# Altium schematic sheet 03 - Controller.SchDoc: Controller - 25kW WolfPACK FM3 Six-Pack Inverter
size 431 x 279 mm; Date: 01/2024; DocumentNumber: CRD25DA12N-FMC; Revision: 1.2; SheetNumber: 3; SheetTotal: 8; SheetSize: B
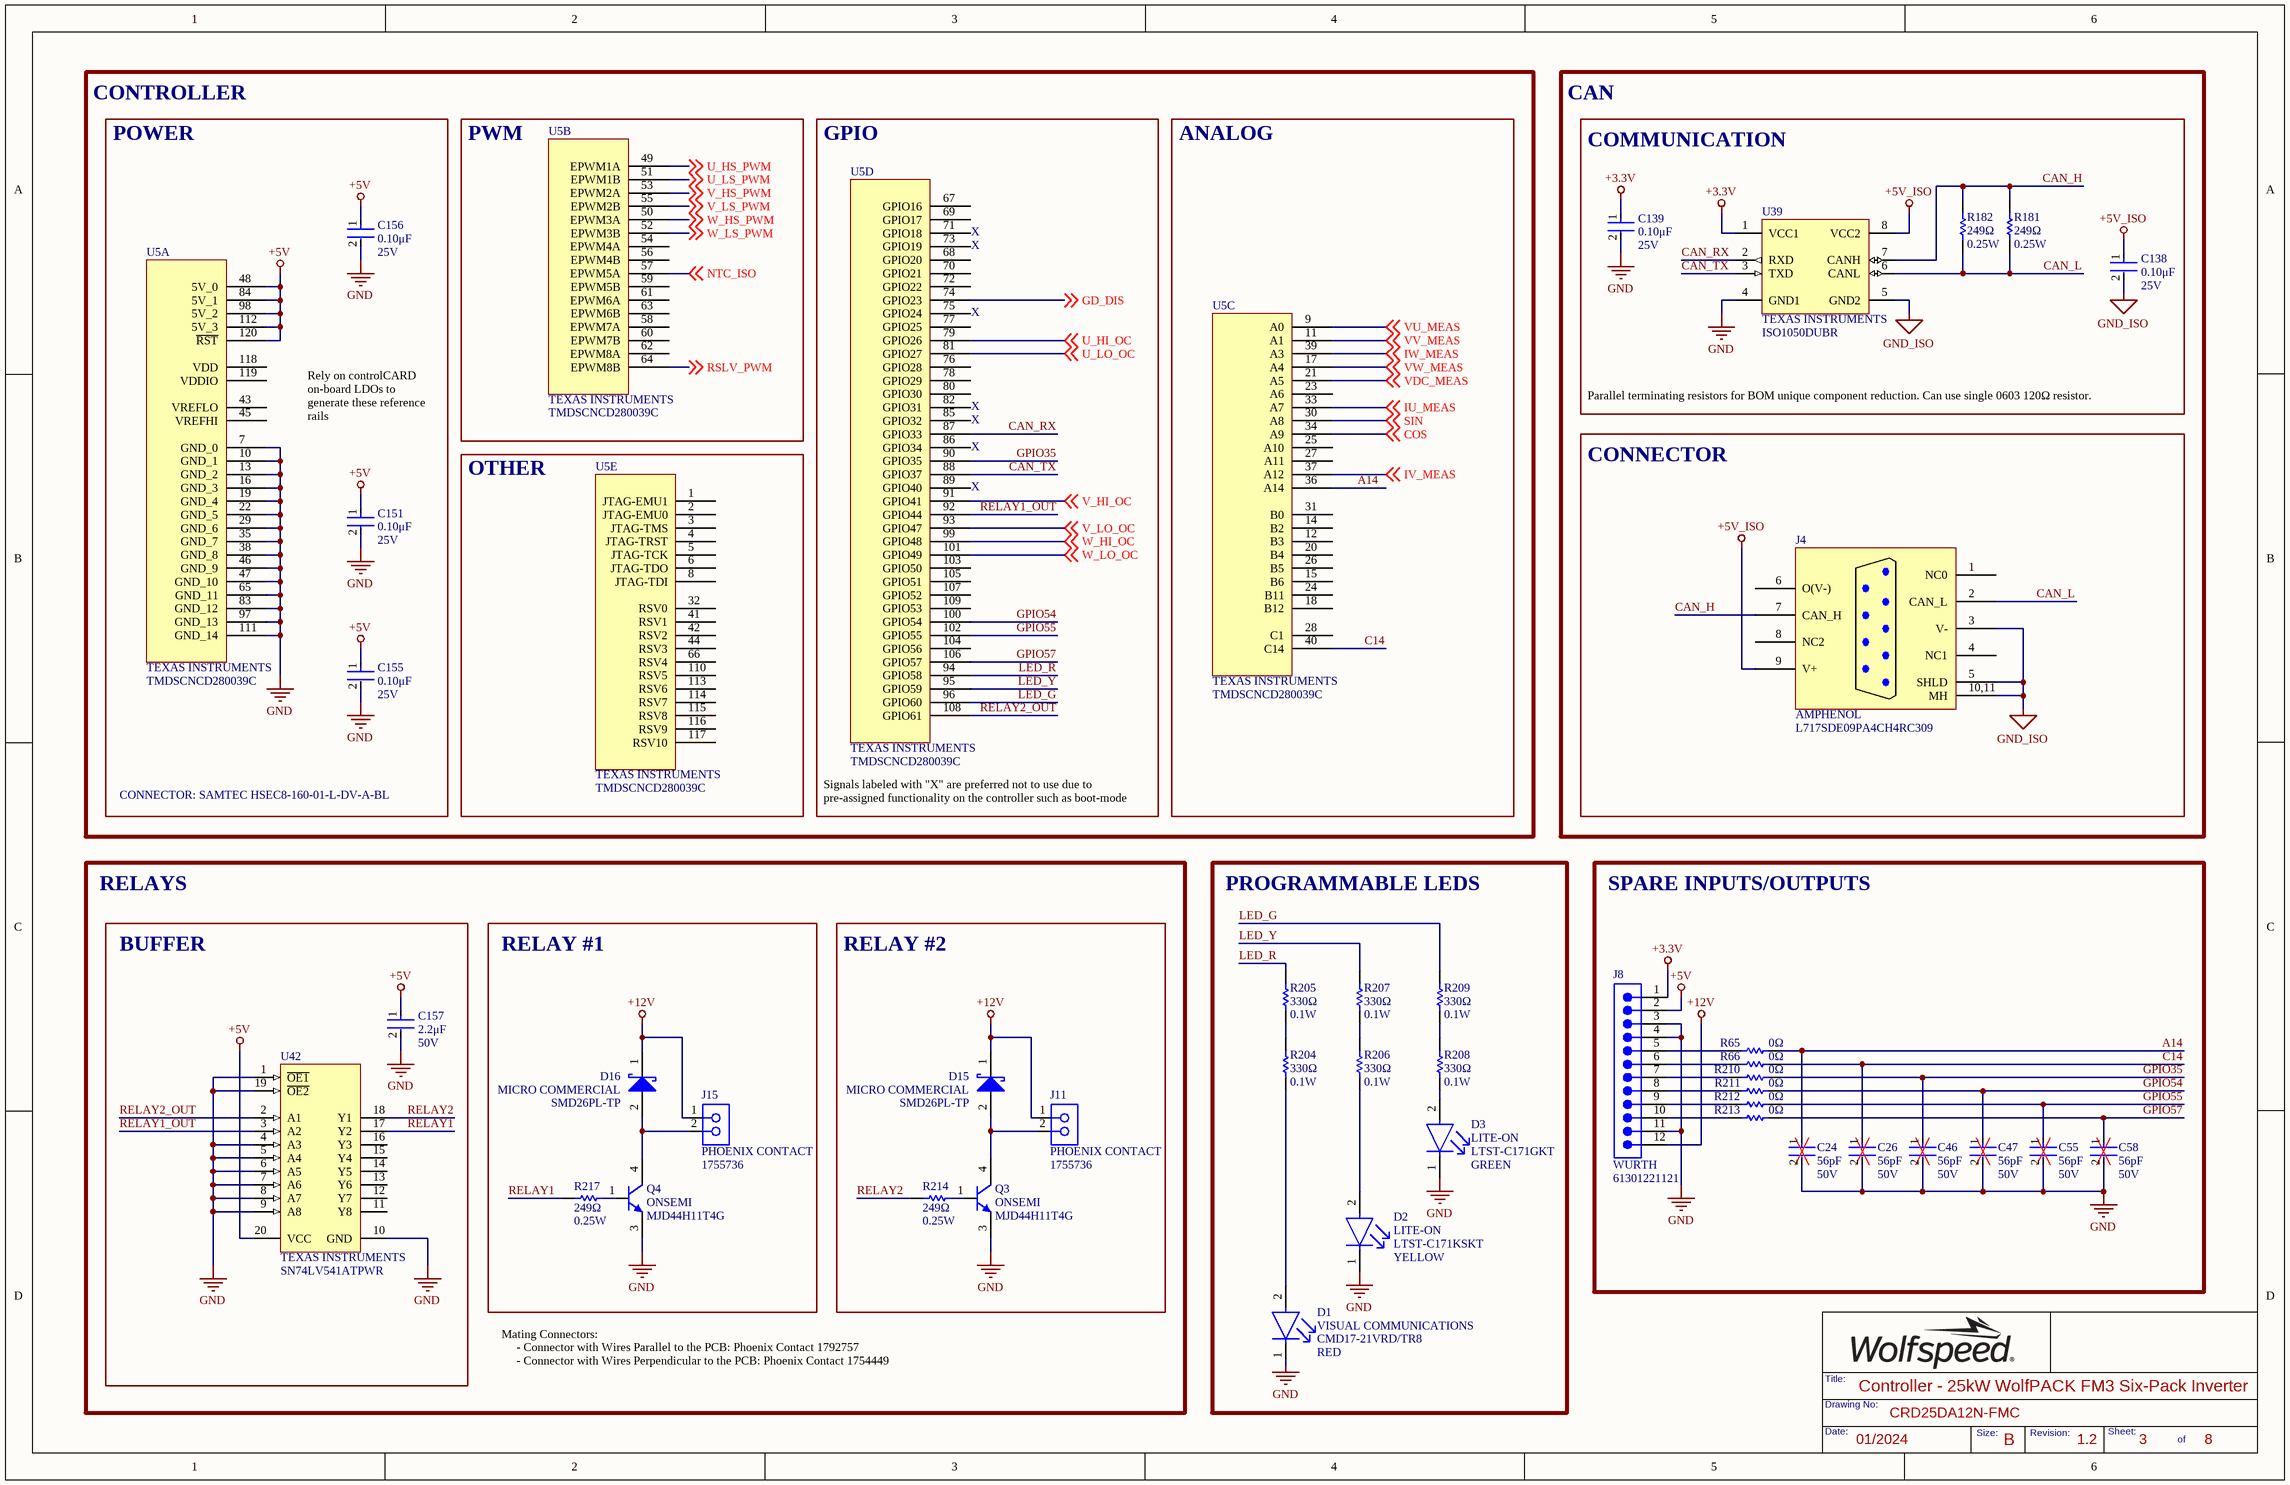
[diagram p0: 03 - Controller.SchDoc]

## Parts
C24  Capacitance: 56pF  Voltage Rating: 50V  [FP-C0603C-CF-IPC_B]  (hidden comment: CL10C560JB8NNNC)
C26  Capacitance: 56pF  Voltage Rating: 50V  [FP-C0603C-CF-IPC_B]  (hidden comment: CL10C560JB8NNNC)
C46  Capacitance: 56pF  Voltage Rating: 50V  [FP-C0603C-CF-IPC_B]  (hidden comment: CL10C560JB8NNNC)
C47  Capacitance: 56pF  Voltage Rating: 50V  [FP-C0603C-CF-IPC_B]  (hidden comment: CL10C560JB8NNNC)
C55  Capacitance: 56pF  Voltage Rating: 50V  [FP-C0603C-CF-IPC_B]  (hidden comment: CL10C560JB8NNNC)
C58  Capacitance: 56pF  Voltage Rating: 50V  [FP-C0603C-CF-IPC_B]  (hidden comment: CL10C560JB8NNNC)
C138  Voltage Rating: 25V  Capacitance: 0.10μF  [FP-C0603C-CF-IPC_B]  (hidden comment: C0603C104K3RACTU)
C139  Voltage Rating: 25V  Capacitance: 0.10μF  [FP-C0603C-CF-IPC_B]  (hidden comment: C0603C104K3RACTU)
C151  Voltage Rating: 25V  Capacitance: 0.10μF  [FP-C0603C-CF-IPC_B]  (hidden comment: C0603C104K3RACTU)
C155  Voltage Rating: 25V  Capacitance: 0.10μF  [FP-C0603C-CF-IPC_B]  (hidden comment: C0603C104K3RACTU)
C156  Voltage Rating: 25V  Capacitance: 0.10μF  [FP-C0603C-CF-IPC_B]  (hidden comment: C0603C104K3RACTU)
C157  Voltage Rating: 50V  Capacitance: 2.2μF  [FP-C0603C-CF-IPC_B]  (hidden comment: GRT188R61H225ME13D)
D1  value RED  Manufacturer: VISUAL COMMUNICATIONS  [FP-LTST-C171GKT-MFG-RED]  (hidden comment: CMD17-21VRD/TR8)
D2  LTST-C171KSKT  value YELLOW  Manufacturer: LITE-ON  [FP-LTST-C171GKT-MFG-YELLOW]
D3  value GREEN  Manufacturer: LITE-ON  [FP-LTST-C171GKT-MFG]  (hidden comment: LTST-C171GKT)
D15  SMD26PL-TP  Manufacturer: MICRO COMMERCIAL  [ONSC-SOD-123FL-2-498-01_V]
D16  SMD26PL-TP  Manufacturer: MICRO COMMERCIAL  [ONSC-SOD-123FL-2-498-01_V]
J4  Manufacturer: AMPHENOL  [L717SDE09PA4CH4RC309]  (hidden comment: L717SDE09PA4CH4RC309)
J8  Manufacturer Print: WURTH  [FP-61301221121-MFG]  (hidden comment: 61301221121)
J11  Manufacturer: PHOENIX CONTACT  [1755736]  (hidden comment: 1755736)
J15  Manufacturer: PHOENIX CONTACT  [1755736]  (hidden comment: 1755736)
Q3  Manufacturer: ONSEMI  [ONSC-DPAK-3-369C-01_V]  (hidden comment: MJD44H11T4G)
Q4  Manufacturer: ONSEMI  [ONSC-DPAK-3-369C-01_V]  (hidden comment: MJD44H11T4G)
R65  Resistance: 0Ω  [FP-MCR03-IPC_B]  (hidden comment: CRCW06030000Z0EB)
R66  Resistance: 0Ω  [FP-MCR03-IPC_B]  (hidden comment: CRCW06030000Z0EB)
R181  Resistance: 249Ω  Power Rating: 0.25W  [FP-MCR18-IPC_A]  (hidden comment: RC1206FR-07249RL)
R182  Resistance: 249Ω  Power Rating: 0.25W  [FP-MCR18-IPC_A]  (hidden comment: RC1206FR-07249RL)
R204  Resistance: 330Ω  Power Rating: 0.1W  [FP-MCR03-IPC_B]  (hidden comment: RC0603FR-13330RL)
R205  Resistance: 330Ω  Power Rating: 0.1W  [FP-MCR03-IPC_B]  (hidden comment: RC0603FR-13330RL)
R206  Resistance: 330Ω  Power Rating: 0.1W  [FP-MCR03-IPC_B]  (hidden comment: RC0603FR-13330RL)
R207  Resistance: 330Ω  Power Rating: 0.1W  [FP-MCR03-IPC_B]  (hidden comment: RC0603FR-13330RL)
R208  Resistance: 330Ω  Power Rating: 0.1W  [FP-MCR03-IPC_B]  (hidden comment: RC0603FR-13330RL)
R209  Resistance: 330Ω  Power Rating: 0.1W  [FP-MCR03-IPC_B]  (hidden comment: RC0603FR-13330RL)
R210  Resistance: 0Ω  [FP-MCR03-IPC_B]  (hidden comment: CRCW06030000Z0EB)
R211  Resistance: 0Ω  [FP-MCR03-IPC_B]  (hidden comment: CRCW06030000Z0EB)
R212  Resistance: 0Ω  [FP-MCR03-IPC_B]  (hidden comment: CRCW06030000Z0EB)
R213  Resistance: 0Ω  [FP-MCR03-IPC_B]  (hidden comment: CRCW06030000Z0EB)
R214  Resistance: 249Ω  Power Rating: 0.25W  [FP-MCR18-IPC_A]  (hidden comment: RC1206FR-07249RL)
R217  Resistance: 249Ω  Power Rating: 0.25W  [FP-MCR18-IPC_A]  (hidden comment: RC1206FR-07249RL)
U5  TMDSCNCD280039C  Manufacturer: TEXAS INSTRUMENTS  [TMDSCNCD280039C]  (parts A,B,C,D,E of 5)
U39  ISO1050DUBR  Manufacturer Print: TEXAS INSTRUMENTS  [DUB0008A_M]
U42  Manufacturer: TEXAS INSTRUMENTS  [PW0020A_L]  (hidden comment: SN74LV541ATPWR)

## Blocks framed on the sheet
POWER: C151 C155 C156 U5
PWM: U5
GPIO: U5
ANALOG: U5
COMMUNICATION: C138 C139 R181 R182 U39
CONNECTOR: J4
OTHER: U5
PROGRAMMABLE LEDS: D1-D3 R204-R209
SPARE INPUTS/OUTPUTS: C24 C26 C46 C47 C55 C58 J8 R65 R66 R210-R213
BUFFER: C157 U42
RELAY #1: D16 J15 Q4 R217
RELAY #2: D15 J11 Q3 R214

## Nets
+3.3V: C139.1 J8.1 U39.1(VCC1)
+5V: C151.1 C155.1 C156.1 C157.1 J8.2 U5.48(5V_0) U5.84(5V_1) U5.98(5V_2) U5.112(5V_3) U5.120(~{RST}) U42.20(VCC)
+5V_ISO: C138.1 J4.9(V+) U39.8(VCC2)
+12V: D15.1(K) D16.1(K) J8.12 J11.1 J15.1
GND: C24.2 C26.2 C46.2 C47.2 C55.2 C58.2 C139.2 C151.2 C155.2 C156.2 C157.2 D1.1(C) D2.1(C) D3.1(C) J8.3 J8.4 J8.11 Q3.3(E) Q4.3(E) U5.7(GND_0) U5.10(GND_1) U5.13(GND_2) U5.16(GND_3) U5.19(GND_4) U5.22(GND_5) U5.29(GND_6) U5.35(GND_7) U5.38(GND_8) U5.46(GND_9) U5.47(GND_10) U5.65(GND_11) U5.83(GND_12) U5.97(GND_13) U5.111(GND_14) U39.4(GND1) U42.1(~{OE1}) U42.4(A3) U42.5(A4) U42.6(A5) U42.7(A6) U42.8(A7) U42.9(A8) U42.10(GND) U42.19(~{OE2})
GND_ISO: C138.2 J4.3(V-) J4.5(SHLD) J4.10,11(MH) U39.5(GND2)
A14: C24.1 R65.2 U5.36(A14)
C14: C26.1 R66.2 U5.40(C14)
CAN_H: J4.7(CAN_H) R181.2 R182.2 U39.7(CANH)
CAN_L: J4.2(CAN_L) R181.1 R182.1 U39.6(CANL)
CAN_RX: U5.87(GPIO33) U39.2(RXD)
CAN_TX: U5.88(GPIO37) U39.3(TXD)
COS: U5.34(A9) ; off-sheet COS
GD_DIS: U5.74(GPIO23) ; off-sheet GD_DIS
GPIO35: C46.1 R210.2 U5.90(GPIO35)
GPIO54: C47.1 R211.2 U5.100(GPIO54)
GPIO55: C55.1 R212.2 U5.102(GPIO55)
GPIO57: C58.1 R213.2 U5.106(GPIO57)
IU_MEAS: U5.33(A7) ; off-sheet IU_MEAS
IV_MEAS: U5.37(A12) ; off-sheet IV_MEAS
IW_MEAS: U5.39(A3) ; off-sheet IW_MEAS
LED_G: R209.2 U5.96(GPIO60)
LED_R: R205.2 U5.94(GPIO58)
LED_Y: R207.2 U5.95(GPIO59)
NTC_ISO: U5.57(EPWM5A) ; off-sheet NTC_ISO
RELAY1: R217.1 U42.17(Y2)
RELAY1_OUT: U5.92(GPIO44) U42.3(A2)
RELAY2: R214.1 U42.18(Y1)
RELAY2_OUT: U5.108(GPIO61) U42.2(A1)
RSLV_PWM: U5.64(EPWM8B) ; off-sheet RSLV_PWM
SIN: U5.30(A8) ; off-sheet SIN
U_HI_OC: U5.79(GPIO26) ; off-sheet U_HI_OC
U_HS_PWM: U5.49(EPWM1A) ; off-sheet U_HS_PWM
U_LO_OC: U5.81(GPIO27) ; off-sheet U_LO_OC
U_LS_PWM: U5.51(EPWM1B) ; off-sheet U_LS_PWM
V_HI_OC: U5.91(GPIO41) ; off-sheet V_HI_OC
V_HS_PWM: U5.53(EPWM2A) ; off-sheet V_HS_PWM
V_LO_OC: U5.93(GPIO47) ; off-sheet V_LO_OC
V_LS_PWM: U5.55(EPWM2B) ; off-sheet V_LS_PWM
VDC_MEAS: U5.21(A5) ; off-sheet VDC_MEAS
VU_MEAS: U5.9(A0) ; off-sheet VU_MEAS
VV_MEAS: U5.11(A1) ; off-sheet VV_MEAS
VW_MEAS: U5.17(A4) ; off-sheet VW_MEAS
W_HI_OC: U5.99(GPIO48) ; off-sheet W_HI_OC
W_HS_PWM: U5.50(EPWM3A) ; off-sheet W_HS_PWM
W_LO_OC: U5.101(GPIO49) ; off-sheet W_LO_OC
W_LS_PWM: U5.52(EPWM3B) ; off-sheet W_LS_PWM
NetD1_2: D1.2(A) R204.1
NetD2_2: D2.2(A) R206.1
NetD3_2: D3.2(A) R208.1
NetD15_2: D15.2(A) J11.2 Q3.4(C)
NetD16_2: D16.2(A) J15.2 Q4.4(C)
NetJ8_5: J8.5 R65.1
NetJ8_6: J8.6 R66.1
NetJ8_7: J8.7 R210.1
NetJ8_8: J8.8 R211.1
NetJ8_9: J8.9 R212.1
NetJ8_10: J8.10 R213.1
NetQ3_1: Q3.1(B) R214.2
NetQ4_1: Q4.1(B) R217.2
NetR204_2: R204.2 R205.1
NetR206_2: R206.2 R207.1
NetR208_2: R208.2 R209.1

Not connected (* = marked no-connect by the designer): J4 1(NC0) 4(NC1) 6(O(V-)) 8(NC2); U5 1(JTAG-EMU1) 2(JTAG-EMU0) 3(JTAG-TMS) 4(JTAG-TRST) 5(JTAG-TCK) 6(JTAG-TDO) 8(JTAG-TDI) 12(B3) 14(B2) 15(B6) 18(B12) 20(B4) 23(A6) 24(B11) 25(A10) 26(B5) 27(A11) 28(C1) 31(B0) 32(RSV0) 41(RSV1) 42(RSV2) 43(VREFLO) 44(RSV3) 45(VREFHI) 54(EPWM4A) 56(EPWM4B) 58(EPWM7A) 59(EPWM5B) 60(EPWM7B) 61(EPWM6A) 62(EPWM8A) 63(EPWM6B) 66(RSV4) 67(GPIO16) 68(GPIO20) 69(GPIO17) 70(GPIO21) 71(GPIO18) 72(GPIO22) 73(GPIO19) 75(GPIO24) 76(GPIO28) 77(GPIO25) 78(GPIO29) 80(GPIO30) 82(GPIO31) 85(GPIO32) 86(GPIO34) 89(GPIO40) 103(GPIO50) 104(GPIO56) 105(GPIO51) 107(GPIO52) 109(GPIO53) 110(RSV5) 113(RSV6) 114(RSV7) 115(RSV8) 116(RSV9) 117(RSV10) 118(VDD) 119(VDDIO); U42 11(Y8) 12(Y7) 13(Y6) 14(Y5) 15(Y4) 16(Y3)

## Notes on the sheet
- CONTROLLER
- CAN
- (near U5) X
- Rely on controlCARD on-board LDOs to generate these reference rails
- Parallel terminating resistors for BOM unique component reduction. Can use single 0603 120Ω resistor.
- CONNECTOR: SAMTEC HSEC8-160-01-L-DV-A-BL
- Signals labeled with "X" are preferred not to use due to pre-assigned functionality on the controller such as boot-mode selection or on-board LEDs
- RELAYS
- Mating Connectors:
  - Connector with Wires Parallel to the PCB: Phoenix Contact 1792757
  - Connector with Wires Perpendicular to the PCB: Phoenix Contact 1754449

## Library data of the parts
C24 C26 C46 C47 C55 C58 = CL10C560JB8NNNC: CAP CER 56PF 50V C0G/NP0 0603; Manufacturer: SAMSUNG; Material: Ceramic; Tolerance: 5%; Dielectric: C0G; Temperature Coefficient: 30ppm/°C
C138 C139 C151 C155 C156 = CMP-2006-03057-2: CAP CER 0.1UF 25V X7R 0603; Manufacturer: KEMET; Value: 0.10μF; Material: Ceramic; Tolerance: 0.1; Temperature Coefficient: 30ppm/°C; Automotive Grade: Grade 1
C157 = GRT188R61H225ME13D: CAP CER 2.2UF 50V X5R 0603; Manufacturer: MURATA; Tolerance: 20%; Value: 2.2μF
D1 = CMD17-21VRD/TR8: LED RED DIFFUSED 0805 SMD; Power Rating: 100mW; Luminous Intensity: 6mcd; Viewing Angle: 140°; Lens Style: Diffused,Tinted,Rectangular,Colored; Forward Current: 20mA; Forward Voltage: 2V; Wavelength: 640nm; Reverse Voltage (DC): 5V; Number of LEDs: 1
D2 = LTST-C171KSKT: LED YELLOW CLEAR 0805 SMD; Lens Color: Colorless; Number of LEDs: 1; Reverse Voltage: 5V; Viewing Angle: 130°; Lens Style: Diffused,Colorless,Rectangular,Clear; Luminous Intensity: 50mcd; Forward Voltage: 2V; Dominant Wavelength: 587nm; Test Current: 20mA; Wavelength: 588nm; Forward Current: 30mA; Max Power Dissipation: 75mW
D3 = CMP-22017-000007-1: LED GREEN CLEAR CHIP SMD; Luminous Intensity: 12mcd; Lens Color: Colorless; Dominant Wavelength: 569nm; Number of LEDs: 1; Power Dissipation: 100mW; Viewing Angle: 130°; Reverse Voltage: 5V; Test Current: 10mA; Forward Voltage: 2.1V; Wavelength: 585nm; Lens Style: Diffused; Forward Current: 30mA
D15 D16 = SMD26PL-TP: DIODE SCHOTTKY 60V 2A SOD123FL; Forward Voltage: 700mV; Max Reverse Current: 500uA; Max Surge Current: 50A; Max Power Dissipation: 1.68W
J4 = L717SDE09PA4CH4RC309: CONN D-SUB PLUG 9POS R/A SLDR; Number of Terminals/Pins: 9; Connector Type: D-Sub,Plug; Voltage Rating: 250V; Current Rating: 5A; Number of Ports: 1; Pitch: 2.74mm
J8 = 61301221121: CONN HEADER VERT 12POS 2.54MM; Manufacturer: WURTH ELEKTRONIK; Number of Positions: 12; Gender: Male; Voltage Rating: 250V; Pitch: 0.1inch
J11 J15 = 1755736: TERM BLOCK HDR 2POS VERT 5.08MM; Content: 250pc(s); Industrial packaging: Yes; Number of contacts: 2
Q3 Q4 = CMP-1046-00010-1: TRANS NPN 80V 8A DPAK; IC Continuous (A): 8; Packing: Tape and Reel
R65 R66 R210-R213 = CRCW06030000Z0EB: RES SMD 0 OHM JUMPER 1/10W 0603; Manufacturer: VISHAY DALE; Manufacturer Part Number: CRCW06030000Z0EBC; Max Power Dissipation: 100mW; Voltage Rating: 75V; Tolerance: 1%; Temperature Coefficient: 100ppm/°C; Value: 0Ω
R181 R182 R214 R217 = RC1206FR-07249RL: RES 249 OHM 1% 1/4W 1206; Manufacturer: YAGEO; Voltage Rating: 200V; Temperature Coefficient: 100ppm/°C; Max Power Dissipation: 250mW; Value: 249Ω
R204-R209 = RC0603FR-13330RL: RES 330 OHM 1% 1/10W 0603; Manufacturer: YAGEO; Voltage Rating: 50V; Temperature Coefficient: 100ppm/°C; Value: 330Ω
U5 = TMDSCNCD280039C: EVAL BOARD FOR TMS320F280039C
U39 = ISO1050DUBR: IC TXRX/ISO HALF 1/1 8SOP; Rating: Catalog; Eco-Plan: Green (RoHS & no Sb/Br); Isolated: Yes; Drivers Per Package: 1; SubFamily: CAN
U42 = CMP-0440-01163-3: IC BUF NON-INVERT 5.5V 20TSSOP; Bits(#): 8; Voltage(Nom)(V): 5; ICC @ Nom Voltage(Max)(mA): 0.02; VCC(Max)(V): 5.5; Output Type: CMOS; Rating: Catalog; Input Type: TTL; VCC(Min)(V): 4.5; F @ Nom Voltage(Max)(Mhz): 110; tpd @ Nom Voltage(Max)(ns): 7.9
